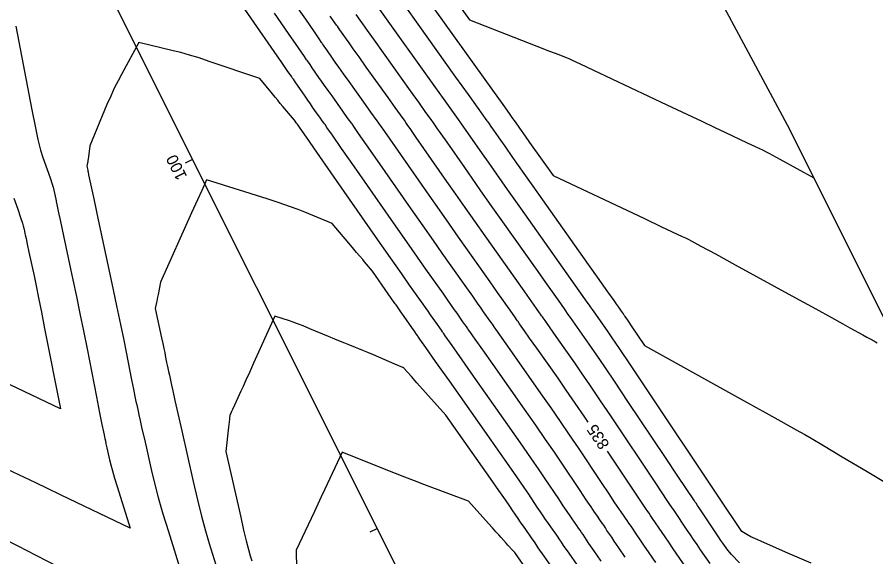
# Model space of a CAD drawing. Extents: x 1715724 to 1716561, y 394063 to 395906.
# Drawn here: x 1716345.4 to 1716449.4, y 394403.2 to 394468.5 of the extents above; entities that cross this region are included whole.
import ezdxf

# ---------------------------------------------------------------- set-up
doc = ezdxf.new("R2010")
doc.units = 0
for name, color, linetype in [('DT_X_Contour_Major', 7, 'Continuous'), ('DT_X_Contour_Minor', 7, 'Continuous'), ('DT_X_TIN_Hull', 7, 'Continuous'), ('GE_P_CL_10', 7, 'Continuous')]:
    doc.layers.add(name, color=color, linetype=linetype)

msp = doc.modelspace()

# ---------------------------------------------------------------- linework, layer by layer
at = {"layer": 'DT_X_Contour_Major'}
for points in [[(1716414.55, 394419.46), (1716414.14, 394420.06), (1716412.98, 394421.76), (1716411.9, 394423.34), (1716410.9, 394424.78), (1716408.32, 394428.44), (1716407.46, 394429.66), (1716406.83, 394430.55), (1716406.25, 394431.39), (1716406.06, 394431.65), (1716405.98, 394431.76), (1716405.87, 394431.92), (1716405.73, 394432.12), (1716405.08, 394433.05), (1716404.79, 394433.46), (1716404.29, 394434.17), (1716403.58, 394435.17), (1716402.66, 394436.48), (1716399.91, 394440.36), (1716398.85, 394441.87), (1716397.73, 394443.47), (1716396.53, 394445.17), (1716395.28, 394446.97), (1716391.84, 394451.89), (1716389.9, 394454.68), (1716389.39, 394455.4), (1716389.2, 394455.67), (1716389.12, 394455.79), (1716389, 394455.96), (1716388.22, 394457.04), (1716387.57, 394457.96), (1716385.59, 394460.72), (1716384.91, 394461.67), (1716384.35, 394462.46), (1716383.91, 394463.09), (1716383.59, 394463.55), (1716382.89, 394464.56), (1716382.66, 394464.9), (1716382.49, 394465.15), (1716382.38, 394465.31), (1716382.32, 394465.38), (1716382.26, 394465.47), (1716382.03, 394465.8), (1716381.38, 394466.74), (1716380.33, 394468.27), (1716378.86, 394470.4)], [(1716395.99, 394469.42), (1716402.94, 394459.7), (1716404.2, 394457.94), (1716404.99, 394456.84), (1716405.31, 394456.39), (1716405.54, 394456.07), (1716405.7, 394455.83), (1716405.78, 394455.72), (1716405.86, 394455.61), (1716406.07, 394455.31), (1716406.22, 394455.1), (1716406.9, 394454.13), (1716407.45, 394453.36), (1716410.29, 394449.34), (1716421.36, 394444.13), (1716423.45, 394443.14), (1716425.95, 394441.97), (1716426.35, 394441.78), (1716426.67, 394441.63), (1716427.12, 394441.39), (1716428.22, 394440.8), (1716429.97, 394439.84), (1716432.37, 394438.53), (1716439.66, 394434.54), (1716442.12, 394433.19), (1716444.04, 394432.14), (1716445.42, 394431.37), (1716446.27, 394430.91), (1716447.81, 394430.05), (1716448.32, 394429.77), (1716448.7, 394429.56), (1716448.95, 394429.42), (1716449.08, 394429.35), (1716449.23, 394429.26), (1716449.35, 394429.2), (1716449.58, 394429.06)], [(1716410.33, 394401.63), (1716409.21, 394403.25), (1716408.51, 394404.26), (1716408.25, 394404.64), (1716408.11, 394404.85), (1716408.03, 394404.96), (1716407.9, 394405.16), (1716407.7, 394405.44), (1716407.45, 394405.8), (1716406.7, 394406.87), (1716406.44, 394407.25), (1716405.99, 394407.91), (1716405.8, 394408.18), (1716405.35, 394408.85), (1716405.06, 394409.28), (1716404.52, 394410.05), (1716403.74, 394411.17), (1716402.71, 394412.64), (1716397.32, 394420.3), (1716393.8, 394424.25), (1716393.14, 394425), (1716392.66, 394425.53), (1716392.27, 394425.97), (1716392.22, 394426.03), (1716392.16, 394426.05), (1716392.15, 394426.06), (1716392.13, 394426.07), (1716392.08, 394426.09), (1716392, 394426.12), (1716391.89, 394426.16), (1716391.6, 394426.29), (1716391.13, 394426.49), (1716390.48, 394426.77), (1716388.53, 394427.62), (1716387.84, 394427.91), (1716387.26, 394428.16), (1716386.77, 394428.36), (1716386.38, 394428.51), (1716385.47, 394428.87), (1716385.07, 394429.03), (1716384.53, 394429.24), (1716383.87, 394429.51), (1716383.09, 394429.84), (1716380.82, 394430.79), (1716380.03, 394431.12), (1716379.35, 394431.38), (1716378.79, 394431.59), (1716378.35, 394431.74), (1716376.57, 394432.31), (1716374.02, 394426.62), (1716373.51, 394425.5), (1716373.09, 394424.56), (1716372.75, 394423.8), (1716372.48, 394423.23), (1716371.9, 394421.96), (1716371.7, 394421.53), (1716371.46, 394421.01), (1716371.41, 394420.9), (1716371.35, 394420.77), (1716371.33, 394420.72), (1716371.31, 394420.66), (1716371.25, 394420.55), (1716371.12, 394420.26), (1716371.12, 394420.16), (1716371.11, 394420.06), (1716371.08, 394419.81), (1716370.98, 394418.86), (1716370.66, 394415.91), (1716372.45, 394407.97), (1716372.81, 394406.4), (1716373.12, 394405.1), (1716373.39, 394404.06), (1716373.61, 394403.29), (1716373.81, 394402.67)], [(1716427.21, 394400.71), (1716424.84, 394404.14), (1716424.31, 394404.91), (1716423.86, 394405.56), (1716423.5, 394406.1), (1716422.35, 394407.81), (1716422.11, 394408.17), (1716421.93, 394408.45), (1716421.79, 394408.64), (1716421.5, 394409.06), (1716421.25, 394409.43), (1716420.7, 394410.24), (1716419.87, 394411.49), (1716418.75, 394413.17), (1716416.88, 394415.96)]]:
    msp.add_lwpolyline(points, dxfattribs=at)
at = {"layer": 'DT_X_Contour_Minor'}
for points in [[(1716395.62, 394474.59), (1716400.19, 394468.2), (1716408.32, 394465.03), (1716409.86, 394464.43), (1716410.98, 394463.99), (1716411.69, 394463.72), (1716411.99, 394463.6), (1716412.22, 394463.51), (1716412.61, 394463.33), (1716413.6, 394462.87), (1716415.2, 394462.11), (1716417.4, 394461.07), (1716424.07, 394457.92), (1716428.33, 394455.91), (1716429.9, 394455.16), (1716431.1, 394454.6), (1716433.81, 394453.32), (1716434.71, 394452.9), (1716435.75, 394452.41), (1716435.9, 394452.34), (1716435.97, 394452.3), (1716436.11, 394452.23), (1716436.45, 394452.04), (1716437.78, 394451.32), (1716441.88, 394449.08)], [(1716419.04, 394403.13), (1716418.27, 394404.25), (1716417.72, 394405.04), (1716417.4, 394405.52), (1716416.83, 394406.36), (1716416.63, 394406.67), (1716416.43, 394406.97), (1716416.24, 394407.25), (1716416.05, 394407.51), (1716415.58, 394408.18), (1716415.32, 394408.56), (1716414.9, 394409.19), (1716414.32, 394410.06), (1716413.57, 394411.17), (1716411.36, 394414.48), (1716410.46, 394415.82), (1716409.4, 394417.36), (1716408.2, 394419.09), (1716406.84, 394421.03), (1716403.03, 394426.45), (1716401.77, 394428.24), (1716400.86, 394429.53), (1716400.3, 394430.33), (1716400.09, 394430.63), (1716399.99, 394430.77), (1716399.92, 394430.87), (1716399.8, 394431.04), (1716399.62, 394431.3), (1716399.38, 394431.64), (1716398.67, 394432.66), (1716398.37, 394433.09), (1716398, 394433.61), (1716397.56, 394434.24), (1716397.05, 394434.96), (1716395.59, 394437.01), (1716394.9, 394438), (1716393.89, 394439.44), (1716392.58, 394441.31), (1716390.96, 394443.63), (1716386.24, 394450.4), (1716384.68, 394452.63), (1716383.57, 394454.22), (1716382.9, 394455.18), (1716382.67, 394455.51), (1716382.64, 394455.55), (1716382.6, 394455.61), (1716382.5, 394455.76), (1716382.33, 394455.98), (1716382.11, 394456.29), (1716381.44, 394457.24), (1716381.17, 394457.61), (1716380.89, 394458.02), (1716380.58, 394458.46), (1716380.25, 394458.94), (1716379.04, 394460.69), (1716378.83, 394461), (1716378.69, 394461.19), (1716378.65, 394461.26), (1716378.63, 394461.29), (1716378.09, 394462.07), (1716377.43, 394463.03), (1716376.5, 394464.37), (1716371.57, 394471.53)], [(1716441.55, 394402.39), (1716438.45, 394403.73), (1716436.2, 394404.71), (1716434.81, 394405.32), (1716434.27, 394405.57), (1716433.76, 394405.87), (1716433.57, 394405.98), (1716433.16, 394406.21), (1716430.38, 394410.38), (1716421.38, 394423.86), (1716419.66, 394426.43), (1716418.35, 394428.38), (1716417.46, 394429.7), (1716416.98, 394430.4), (1716415.48, 394432.53), (1716415.07, 394433.11), (1716414.84, 394433.44), (1716414.7, 394433.64), (1716414.43, 394434.02), (1716406.39, 394445.39), (1716404.78, 394447.67), (1716403.48, 394449.52), (1716402.47, 394450.96), (1716401.75, 394451.97), (1716399.13, 394455.73), (1716398.83, 394456.15), (1716390.53, 394467.77), (1716388.91, 394470.03)], [(1716422.74, 394402.47), (1716421.94, 394403.63), (1716421.29, 394404.58), (1716420.79, 394405.3), (1716420.45, 394405.81), (1716419.74, 394406.87), (1716419.49, 394407.24), (1716419.27, 394407.57), (1716419.08, 394407.85), (1716418.92, 394408.08), (1716418.54, 394408.62), (1716418.28, 394409), (1716417.8, 394409.71), (1716417.09, 394410.77), (1716416.16, 394412.17), (1716413.36, 394416.35), (1716412.3, 394417.94), (1716411.19, 394419.56), (1716410.05, 394421.21), (1716408.87, 394422.9), (1716405.67, 394427.45), (1716404.62, 394428.95), (1716403.85, 394430.04), (1716403.36, 394430.73), (1716403.17, 394431.01), (1716403.02, 394431.21), (1716402.95, 394431.32), (1716402.83, 394431.48), (1716402.67, 394431.71), (1716402.47, 394432), (1716401.87, 394432.85), (1716401.58, 394433.27), (1716401.15, 394433.89), (1716400.57, 394434.71), (1716399.85, 394435.72), (1716397.75, 394438.69), (1716396.87, 394439.94), (1716395.81, 394441.46), (1716394.56, 394443.24), (1716393.12, 394445.3), (1716389.04, 394451.15), (1716387.7, 394453.07), (1716386.73, 394454.45), (1716386.15, 394455.29), (1716385.94, 394455.59), (1716385.88, 394455.67), (1716385.8, 394455.79), (1716385.6, 394456.07), (1716385.28, 394456.51), (1716384.84, 394457.13), (1716383.52, 394458.98), (1716383.04, 394459.64), (1716382.62, 394460.24), (1716382.24, 394460.78), (1716381.92, 394461.24), (1716381.12, 394462.41), (1716380.85, 394462.79), (1716380.54, 394463.25), (1716380.48, 394463.32), (1716380.44, 394463.38), (1716380.19, 394463.75), (1716379.46, 394464.81), (1716378.24, 394466.57), (1716376.55, 394469.02)], [(1716392.4, 394469.8), (1716393.91, 394467.68), (1716398.49, 394461.28), (1716400, 394459.17), (1716401.1, 394457.63), (1716401.79, 394456.66), (1716402.07, 394456.27), (1716402.27, 394455.99), (1716402.38, 394455.84), (1716402.54, 394455.6), (1716402.77, 394455.28), (1716403.06, 394454.86), (1716403.91, 394453.64), (1716404.44, 394452.89), (1716405.39, 394451.54), (1716406.76, 394449.6), (1716408.55, 394447.07), (1716413.88, 394439.52), (1716415.64, 394437.05), (1716416.89, 394435.27), (1716417.64, 394434.2), (1716417.9, 394433.84), (1716417.93, 394433.8), (1716417.96, 394433.76), (1716418.01, 394433.68), (1716418.1, 394433.56), (1716418.21, 394433.4), (1716418.56, 394432.9), (1716418.68, 394432.74), (1716418.78, 394432.6), (1716418.85, 394432.49), (1716418.9, 394432.42), (1716419.01, 394432.27), (1716419.09, 394432.16), (1716419.24, 394431.93), (1716419.47, 394431.59), (1716419.77, 394431.13), (1716421.37, 394428.74), (1716433.72, 394421.89), (1716436.08, 394420.58), (1716437.88, 394419.58), (1716439.11, 394418.9), (1716439.77, 394418.53), (1716440.79, 394417.96), (1716441.55, 394417.52), (1716443.06, 394416.63), (1716445.33, 394415.28), (1716448.35, 394413.48), (1716464.23, 394404.01)], [(1716429.33, 394402.33), (1716428.17, 394404.01), (1716427.74, 394404.64), (1716427.33, 394405.24), (1716426.93, 394405.83), (1716426.55, 394406.39), (1716424.96, 394408.77), (1716424.66, 394409.21), (1716424.46, 394409.5), (1716424.21, 394409.87), (1716422.65, 394412.21), (1716417.37, 394420.11), (1716415.98, 394422.18), (1716414.77, 394423.97), (1716413.75, 394425.46), (1716412.93, 394426.65), (1716410.96, 394429.44), (1716410.31, 394430.37), (1716409.49, 394431.53), (1716409.32, 394431.77), (1716409.1, 394432.09), (1716409.01, 394432.21), (1716408.9, 394432.36), (1716408.79, 394432.53), (1716408.65, 394432.72), (1716408.29, 394433.25), (1716408.01, 394433.64), (1716407.44, 394434.44), (1716406.6, 394435.64), (1716402.07, 394442.04), (1716400.83, 394443.8), (1716399.64, 394445.49), (1716398.51, 394447.1), (1716397.44, 394448.64), (1716393.73, 394453.95), (1716393.06, 394454.91), (1716392.64, 394455.51), (1716392.47, 394455.75), (1716392.36, 394455.91), (1716391.8, 394456.69), (1716391.17, 394457.57), (1716390.3, 394458.79), (1716387.67, 394462.46), (1716386.79, 394463.71), (1716386.09, 394464.69), (1716385.58, 394465.4), (1716385.26, 394465.86), (1716384.67, 394466.71), (1716384.47, 394467), (1716384.32, 394467.22), (1716384.16, 394467.45), (1716384.07, 394467.56), (1716383.87, 394467.86), (1716383.31, 394468.66)], [(1716432.89, 394402.43), (1716431.92, 394403.42), (1716431.46, 394403.96), (1716430.88, 394404.79), (1716430.64, 394405.14), (1716430.35, 394405.57), (1716429.6, 394406.68), (1716428.08, 394408.95), (1716427.8, 394409.38), (1716427.62, 394409.65), (1716427.53, 394409.78), (1716427.42, 394409.94), (1716425.42, 394412.92), (1716423.92, 394415.17), (1716419.37, 394421.98), (1716417.82, 394424.31), (1716416.56, 394426.17), (1716415.61, 394427.58), (1716414.95, 394428.52), (1716412.4, 394432.15), (1716412.14, 394432.52), (1716411.75, 394433.08), (1716411.22, 394433.83), (1716409.61, 394436.11), (1716408.27, 394438), (1716404.23, 394443.72), (1716402.81, 394445.73), (1716401.56, 394447.51), (1716400.49, 394449.03), (1716399.6, 394450.31), (1716397.45, 394453.38), (1716396.74, 394454.39), (1716396.22, 394455.14), (1716395.88, 394455.62), (1716395.74, 394455.83), (1716395.59, 394456.03), (1716395.39, 394456.31), (1716394.9, 394457), (1716394.11, 394458.11), (1716393.03, 394459.62), (1716389.75, 394464.2), (1716388.66, 394465.74), (1716387.82, 394466.91), (1716387.25, 394467.72), (1716386.93, 394468.16), (1716386.45, 394468.87)], [(1716345.2, 394467.44), (1716347.14, 394457.3), (1716347.54, 394455.31), (1716347.89, 394453.69), (1716348.21, 394452.43), (1716348.48, 394451.53), (1716349.16, 394449.62), (1716349.4, 394448.96), (1716349.58, 394448.4), (1716349.72, 394447.93), (1716349.81, 394447.57), (1716350.04, 394446.47), (1716350.09, 394446.26), (1716350.11, 394446.14), (1716350.13, 394446.09), (1716350.13, 394446.05), (1716350.35, 394445.03), (1716350.62, 394443.78), (1716350.99, 394442.03), (1716352.13, 394436.72), (1716352.55, 394434.7), (1716352.98, 394432.64), (1716353.41, 394430.52), (1716353.84, 394428.36), (1716354.98, 394422.52), (1716355.36, 394420.6), (1716355.64, 394419.19), (1716355.81, 394418.3), (1716355.89, 394417.93), (1716355.95, 394417.65), (1716355.99, 394417.49), (1716356.05, 394417.22), (1716356.13, 394416.84), (1716356.24, 394416.35), (1716356.57, 394414.91), (1716356.72, 394414.3), (1716356.92, 394413.55), (1716357.18, 394412.68), (1716357.49, 394411.66), (1716359.06, 394406.63), (1716350.7, 394410.63), (1716349.03, 394411.43), (1716347.63, 394412.1), (1716345.58, 394413.07), (1716343.53, 394414.05)], [(1716416.14, 394402.63), (1716415.25, 394403.92), (1716414.65, 394404.78), (1716414.35, 394405.23), (1716413.93, 394405.86), (1716413.76, 394406.1), (1716413.58, 394406.37), (1716413.39, 394406.64), (1716413.19, 394406.94), (1716412.62, 394407.75), (1716412.36, 394408.13), (1716412, 394408.66), (1716411.54, 394409.34), (1716410.98, 394410.17), (1716409.36, 394412.6), (1716408.62, 394413.7), (1716407.62, 394415.15), (1716406.35, 394416.97), (1716404.82, 394419.15), (1716400.38, 394425.46), (1716398.92, 394427.53), (1716397.87, 394429.02), (1716397.24, 394429.93), (1716397.01, 394430.25), (1716396.95, 394430.33), (1716396.89, 394430.42), (1716396.76, 394430.6), (1716396.56, 394430.89), (1716396.29, 394431.28), (1716395.46, 394432.46), (1716395.15, 394432.9), (1716394.85, 394433.34), (1716394.54, 394433.77), (1716394.24, 394434.2), (1716393.44, 394435.34), (1716392.92, 394436.07), (1716391.98, 394437.42), (1716390.6, 394439.39), (1716388.8, 394441.96), (1716383.43, 394449.66), (1716381.67, 394452.19), (1716380.41, 394453.99), (1716379.66, 394455.07), (1716379.4, 394455.43), (1716379.4, 394455.44), (1716379.4, 394455.44), (1716379.4, 394455.44), (1716379.39, 394455.45), (1716379.38, 394455.46), (1716379.36, 394455.5), (1716379.34, 394455.52), (1716379.31, 394455.56), (1716379.28, 394455.61), (1716379.23, 394455.68), (1716378.98, 394456.04), (1716377.55, 394457.72), (1716377.25, 394458.09), (1716376.93, 394458.46), (1716376.61, 394458.85), (1716376.29, 394459.24), (1716374.75, 394461.11), (1716368.65, 394463.17), (1716367.4, 394463.59), (1716366.25, 394463.94), (1716365.2, 394464.24), (1716364.26, 394464.47), (1716360.11, 394465.44), (1716358.03, 394461.67), (1716357.59, 394460.83), (1716357.14, 394459.93), (1716356.7, 394458.96), (1716356.25, 394457.93), (1716354.17, 394452.96), (1716354, 394451.62), (1716353.97, 394451.36), (1716353.94, 394451.15), (1716353.91, 394450.99), (1716353.89, 394450.88), (1716353.8, 394450.47), (1716353.91, 394449.99), (1716353.93, 394449.89), (1716353.94, 394449.83), (1716353.95, 394449.79), (1716353.95, 394449.78), (1716353.95, 394449.77), (1716354.03, 394449.41), (1716354.26, 394448.32), (1716354.65, 394446.51), (1716355.19, 394443.98), (1716356.84, 394436.25), (1716357.42, 394433.56), (1716357.9, 394431.28), (1716358.28, 394429.41), (1716358.57, 394427.95), (1716359.23, 394424.61), (1716359.45, 394423.48), (1716359.63, 394422.59), (1716359.76, 394421.95), (1716359.85, 394421.55), (1716360.01, 394420.8), (1716360.11, 394420.37), (1716360.27, 394419.66), (1716360.49, 394418.67), (1716360.78, 394417.39), (1716361.64, 394413.59), (1716362.01, 394412.06), (1716362.47, 394410.32), (1716363.03, 394408.37), (1716363.69, 394406.22), (1716365.58, 394400.19)], [(1716413.24, 394402.13), (1716412.23, 394403.58), (1716411.58, 394404.52), (1716411.3, 394404.94), (1716411.02, 394405.35), (1716410.9, 394405.53), (1716410.74, 394405.76), (1716410.55, 394406.04), (1716410.32, 394406.37), (1716409.66, 394407.31), (1716409.4, 394407.69), (1716409.1, 394408.13), (1716408.76, 394408.62), (1716408.39, 394409.18), (1716407.36, 394410.73), (1716406.78, 394411.57), (1716405.83, 394412.95), (1716404.5, 394414.85), (1716402.79, 394417.28), (1716397.73, 394424.46), (1716396.07, 394426.82), (1716394.89, 394428.51), (1716394.17, 394429.53), (1716393.93, 394429.87), (1716393.91, 394429.9), (1716393.86, 394429.97), (1716393.73, 394430.16), (1716393.5, 394430.48), (1716393.19, 394430.92), (1716392.26, 394432.26), (1716391.94, 394432.71), (1716391.7, 394433.06), (1716391.53, 394433.3), (1716391.43, 394433.44), (1716391.28, 394433.66), (1716391.17, 394433.81), (1716390.98, 394434.08), (1716390.7, 394434.48), (1716390.33, 394435.01), (1716388.41, 394437.77), (1716387.47, 394438.89), (1716387.23, 394439.18), (1716386.9, 394439.56), (1716386.5, 394440.04), (1716386.01, 394440.62), (1716383.53, 394443.53), (1716380.23, 394444.92), (1716379.42, 394445.24), (1716378.38, 394445.61), (1716377.13, 394446.03), (1716375.67, 394446.51), (1716368.32, 394448.84), (1716368.18, 394448.54), (1716368.06, 394448.26), (1716367.73, 394447.55), (1716367.22, 394446.4), (1716366.51, 394444.82), (1716362.74, 394436.43), (1716362.45, 394434.92), (1716362.39, 394434.61), (1716362.34, 394434.35), (1716362.3, 394434.14), (1716362.26, 394433.96), (1716362.1, 394433.25), (1716362.86, 394429.7), (1716363.01, 394428.99), (1716363.14, 394428.4), (1716363.24, 394427.92), (1716363.31, 394427.54), (1716363.48, 394426.7), (1716363.54, 394426.37), (1716363.62, 394426), (1716363.71, 394425.59), (1716363.81, 394425.16), (1716364.08, 394423.95), (1716364.23, 394423.26), (1716364.49, 394422.11), (1716364.85, 394420.5), (1716365.32, 394418.42), (1716366.71, 394412.27), (1716367.22, 394410.07), (1716367.71, 394408.08), (1716368.19, 394406.31), (1716368.65, 394404.75), (1716369.86, 394400.89)], [(1716344.96, 394446.62), (1716345.44, 394445.28), (1716345.79, 394444.27), (1716346.02, 394443.59), (1716346.11, 394443.25), (1716346.21, 394442.8), (1716346.25, 394442.64), (1716346.27, 394442.53), (1716346.29, 394442.44), (1716346.3, 394442.4), (1716346.31, 394442.32), (1716346.35, 394442.16), (1716346.44, 394441.73), (1716346.59, 394441.04), (1716346.79, 394440.08), (1716347.41, 394437.19), (1716347.66, 394435.97), (1716347.96, 394434.51), (1716348.31, 394432.8), (1716348.69, 394430.83), (1716350.61, 394421.08), (1716344.5, 394423.97)], [(1716414.63, 394390.76), (1716405.67, 394403.67), (1716405.44, 394403.91), (1716405.39, 394403.96), (1716405.35, 394404), (1716405.3, 394404.05), (1716405.26, 394404.09), (1716405.16, 394404.21), (1716405.1, 394404.28), (1716404.98, 394404.4), (1716404.82, 394404.58), (1716404.61, 394404.81), (1716403.99, 394405.51), (1716403.71, 394405.81), (1716403.37, 394406.19), (1716402.96, 394406.65), (1716402.47, 394407.19), (1716400.04, 394409.89), (1716394.64, 394411.93), (1716393.49, 394412.36), (1716392.34, 394412.81), (1716391.2, 394413.25), (1716390.06, 394413.7), (1716384.76, 394415.82), (1716382.66, 394411.36), (1716382.22, 394410.42), (1716381.79, 394409.52), (1716381.38, 394408.64), (1716380.99, 394407.8), (1716379.19, 394403.94), (1716379.2, 394401.65)], [(1716350.48, 394401.87), (1716347.66, 394403.33), (1716345.49, 394404.45), (1716343.95, 394405.23)]]:
    msp.add_lwpolyline(points, dxfattribs=at)
at = {"layer": 'DT_X_TIN_Hull'}
msp.add_lwpolyline([(1716463.55, 394299.53), (1716471.86, 394306.26), (1716483.85, 394306.75), (1716504.79, 394314.54), (1716501.89, 394321.94), (1716496.82, 394331.94), (1716489.52, 394351.03), (1716488, 394358.9), (1716476.67, 394377.28), (1716464.97, 394402.5), (1716450.77, 394431.32), (1716438.69, 394455.43), (1716425.17, 394480.67), (1716411.91, 394506.87), (1716399.57, 394530.29)], dxfattribs=at)
at = {"layer": 'GE_P_CL_10'}
for p, q in [((1716447.81, 394289.08), (1716249.46, 394685.42)), ((1716366.63, 394451.29), (1716365.74, 394450.85)), ((1716389.01, 394406.58), (1716388.11, 394406.13))]:
    msp.add_line(p, q, dxfattribs=at)

# ---------------------------------------------------------------- texts
at = {"layer": 'DT_X_Contour_Major'}
msp.add_text('835', height=1.4, rotation=123.7796, dxfattribs=at).set_placement((1716417.19, 394416.77))
at = {"layer": 'GE_P_CL_10'}
msp.add_text('100', height=1.4, rotation=116.5857, dxfattribs=at).set_placement((1716365.99, 394449.23))

doc.saveas('drawing.dxf')
